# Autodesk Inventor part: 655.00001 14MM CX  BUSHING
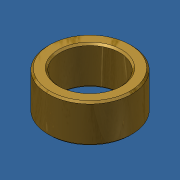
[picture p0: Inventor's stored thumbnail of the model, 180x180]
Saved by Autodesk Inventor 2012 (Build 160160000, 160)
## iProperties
Created: 2013-10
Part Number: 655.00001 14MM CX  BUSHING
Material: BRASS 340
Document SubType Name: Modeling
Designer: Admin
Density: 8.47 g/cm^3
Mass: 4.23228 g
Surface Area: 6.25632 cm^2
Volume: 0.499679 cm^3
Author: Admin
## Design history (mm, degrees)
node "655.00001 14MM CX  BUSHING1"
node "Base1"
body "Solid1"
